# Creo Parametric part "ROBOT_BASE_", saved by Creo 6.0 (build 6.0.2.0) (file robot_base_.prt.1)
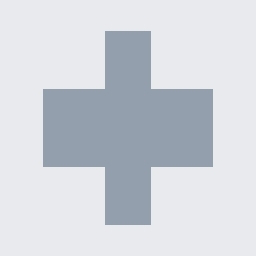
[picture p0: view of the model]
Units: Inch lbm Second (Pro/E Default); INCH, POUND, SECS

Created from: INLBS_PART_SOLID.PRT

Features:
  1. datum plane "RIGHT"
  2. datum plane "TOP"
  3. datum plane "FRONT"
  4. coordinate system
  5. sketch "Sketch 1"
  6. extrusion "Extrude 1"

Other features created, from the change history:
  sketch "Sketch 1"
  extrusion "Extrude 1"

Surfaces: 14 plane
